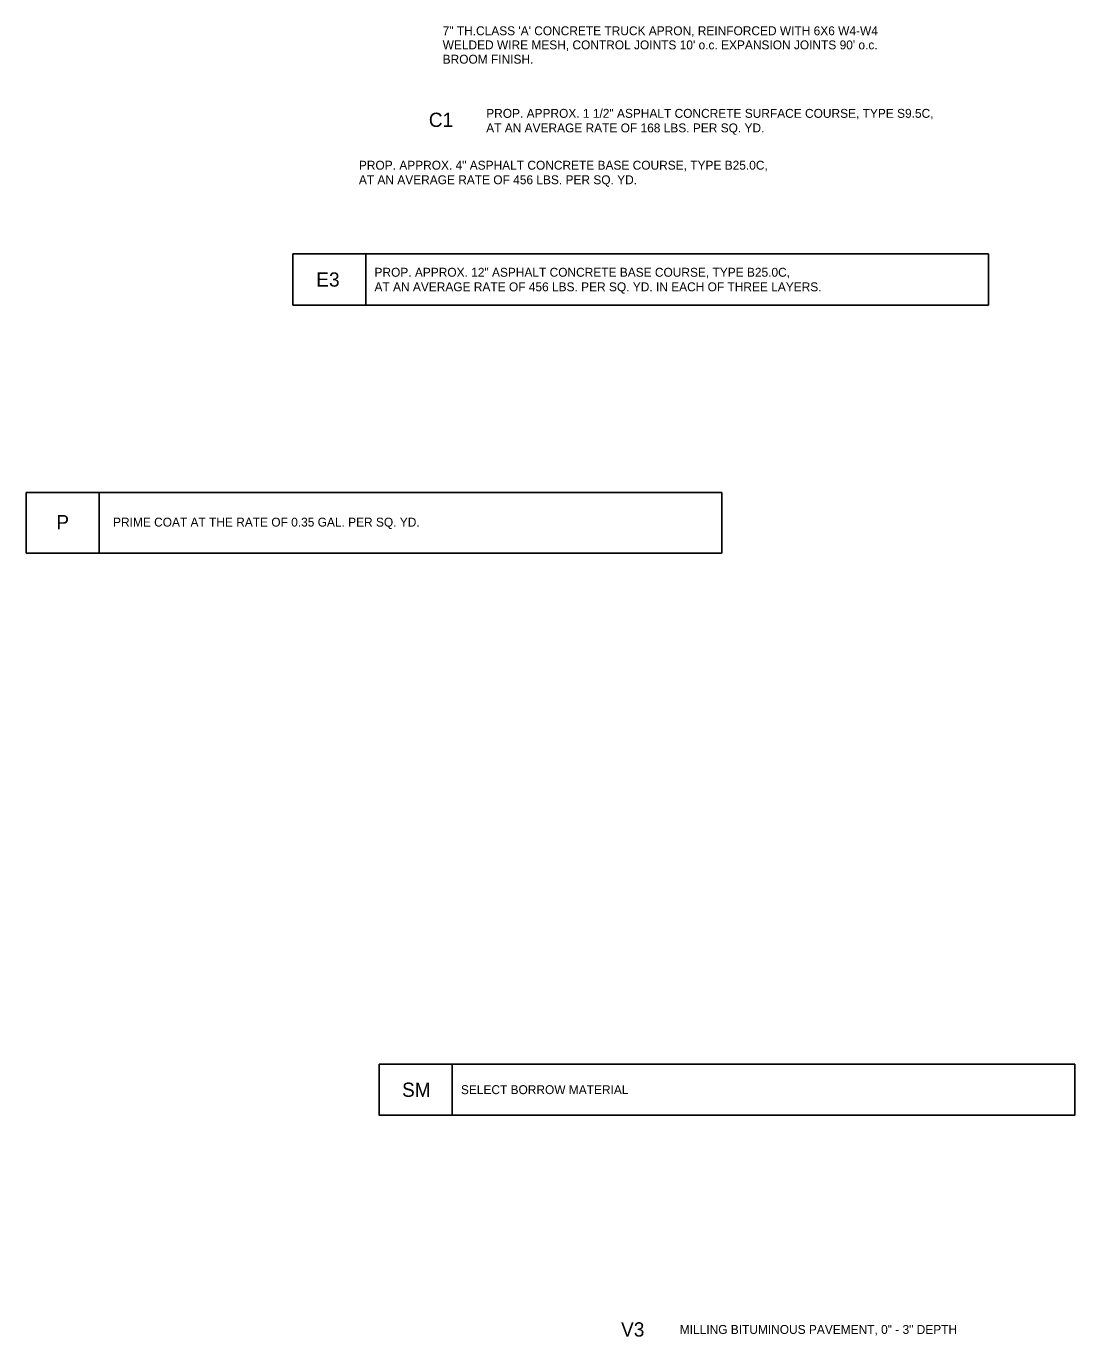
# Model space of a CAD drawing. Extents: x 573748 to 574632, y -54663 to -53209.
# Drawn here: x 573783.6 to 573930.6, y -53407.2 to -53223.4 of the extents above; entities that cross this region are included whole.
import ezdxf

# ---------------------------------------------------------------- set-up
doc = ezdxf.new("R2010")
doc.units = 0
doc.layers.add('Prop Pavement Schedule Description CELL', color=7, linetype='Continuous')

msp = doc.modelspace()

# ---------------------------------------------------------------- linework, layer by layer
at = {"layer": 'Prop Pavement Schedule Description CELL'}
for points in [[(573831.19, -53262.52), (573820.97, -53262.52), (573820.97, -53255.36), (573918.52, -53255.36), (573918.52, -53262.52), (573831.19, -53262.52), (573831.19, -53255.36)], [(573793.79, -53297.29), (573783.57, -53297.29), (573783.57, -53288.82), (573881.12, -53288.82), (573881.12, -53297.29), (573793.79, -53297.29), (573793.79, -53288.82)], [(573843.31, -53376.1), (573833.08, -53376.1), (573833.08, -53368.95), (573930.64, -53368.95), (573930.64, -53376.1), (573843.31, -53376.1), (573843.31, -53368.95)]]:
    msp.add_lwpolyline(points, dxfattribs=at)

# ---------------------------------------------------------------- texts
for s, height, p in [('7" TH.CLASS \'A\' CONCRETE TRUCK APRON, REINFORCED WITH 6X6 W4-W4', 1.25, (573841.98, -53224.69)), ("WELDED WIRE MESH, CONTROL JOINTS 10' o.c. EXPANSION JOINTS 90' o.c.", 1.25, (573841.98, -53226.67)), ('BROOM FINISH.', 1.25, (573841.98, -53228.68)), ('C1', 2, (573840.04, -53237.55)), ('PROP. APPROX. 1 1/2" ASPHALT CONCRETE SURFACE COURSE, TYPE S9.5C, ', 1.25, (573848.09, -53236.27)), ('AT AN AVERAGE RATE OF 168 LBS. PER SQ. YD.', 1.25, (573848.09, -53238.31)), ('PROP. APPROX. 4" ASPHALT CONCRETE BASE COURSE, TYPE B25.0C,', 1.25, (573830.23, -53243.54)), ('AT AN AVERAGE RATE OF 456 LBS. PER SQ. YD.', 1.25, (573830.23, -53245.58)), ('E3', 2, (573824.25, -53259.94)), ('PROP. APPROX. 12" ASPHALT CONCRETE BASE COURSE, TYPE B25.0C,', 1.25, (573832.42, -53258.55)), ('AT AN AVERAGE RATE OF 456 LBS. PER SQ. YD. IN EACH OF THREE LAYERS.', 1.25, (573832.42, -53260.59)), ('P', 2, (573787.79, -53293.96)), ('SM', 2, (573836.28, -53373.53)), ('SELECT BORROW MATERIAL', 1.25, (573844.54, -53373.15)), ('V3', 2, (573867, -53407.14)), ('MILLING BITUMINOUS PAVEMENT, 0" - 3" DEPTH', 1.25, (573875.24, -53406.77))]:
    msp.add_text(s, height=height, dxfattribs=at).set_placement(p)
msp.add_text('PRIME COAT AT THE RATE OF 0.35 GAL. PER SQ. YD.', height=1.25, rotation=360, dxfattribs=at).set_placement((573795.75, -53293.58))

doc.saveas('drawing.dxf')
